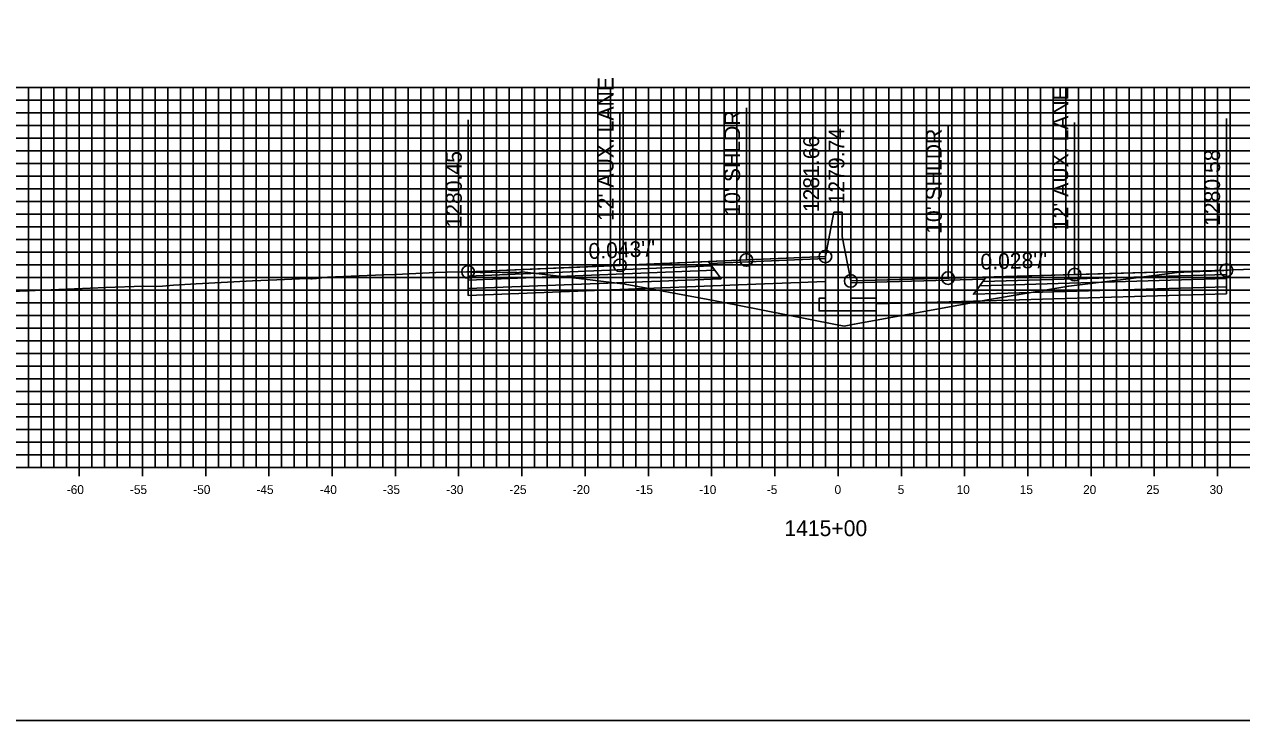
# Model space of a CAD drawing. Extents: x 674939 to 678919, y 750652 to 765176.
# Drawn here: x 678674.2 to 678770.4, y 757362.6 to 757417.6 of the extents above; entities that cross this region are included whole.
import ezdxf

# ---------------------------------------------------------------- set-up
doc = ezdxf.new("R2010")
doc.units = 0
for name, color, linetype in [('Level 10', 7, 'Continuous'), ('Level 17', 7, 'Continuous'), ('Level 18', 7, 'Continuous'), ('Level 19', 7, 'Continuous'), ('Level 20', 7, 'Continuous'), ('Level 22', 7, 'Continuous'), ('Level 23', 7, 'Continuous'), ('Level 4', 7, 'Continuous'), ('Level 8', 7, 'Continuous'), ('Level 9', 7, 'Continuous')]:
    doc.layers.add(name, color=color, linetype=linetype)

msp = doc.modelspace()

# ---------------------------------------------------------------- linework, layer by layer
at = {"layer": 'Level 10'}
msp.add_lwpolyline([(678673.204, 757396.454), (678680.637, 757396.759), (678683.613, 757396.86), (678684.619, 757396.855), (678685.125, 757396.867), (678685.988, 757396.947), (678687.79, 757397.046), (678692.244, 757397.286), (678693.542, 757397.337), (678696.557, 757397.466), (678696.844, 757397.454), (678696.957, 757397.449), (678697.296, 757397.481), (678698.157, 757397.57), (678701.312, 757397.704), (678702.614, 757397.757), (678703.576, 757397.798), (678706.73, 757397.946), (678707.615, 757397.971), (678709.191, 757398.006), (678709.281, 757398.001), (678709.304, 757398.002), (678709.474, 757397.988), (678710.244, 757397.952), (678710.471, 757397.951), (678710.641, 757397.958), (678711.644, 757397.973), (678711.984, 757397.962), (678712.987, 757397.938), (678713.101, 757397.938), (678713.158, 757397.933), (678713.301, 757397.946), (678713.424, 757397.975), (678713.567, 757398.013), (678719.143, 757397.336), (678721.689, 757397.02), (678728.253, 757395.813), (678730.436, 757395.408), (678738.318, 757393.85), (678739.006, 757393.714), (678739.804, 757393.856), (678748.937, 757395.534), (678750.191, 757395.754), (678756.762, 757396.881), (678761.483, 757397.458), (678765.331, 757397.947), (678766.427, 757397.99), (678767.839, 757398.06), (678768.056, 757398.056), (678768.514, 757398.074), (678769.02, 757398.115), (678769.228, 757398.127), (678769.372, 757398.139), (678769.715, 757398.158), (678771.464, 757398.211)], dxfattribs=at)
at = {"layer": 'Level 17'}
for points in [[(678738.203, 757402.714), (678737.533, 757399.214)], [(678738.203, 757402.714), (678738.203, 757402.714)], [(678738.203, 757402.714), (678738.863, 757402.714)], [(678738.863, 757402.714), (678738.863, 757400.787)], [(678738.863, 757400.787), (678739.533, 757397.287)], [(678737.533, 757399.214), (678737.533, 757395.912), (678737.033, 757395.912), (678737.033, 757394.912), (678741.533, 757394.912), (678741.533, 757395.912), (678739.533, 757395.912), (678739.533, 757397.287)]]:
    msp.add_lwpolyline(points, dxfattribs=at)
at = {"layer": 'Level 18'}
for points in [[(678737.533, 757399.214), (678731.281, 757398.945), (678721.281, 757398.516), (678709.281, 757398.001)], [(678769.228, 757398.127), (678757.228, 757397.787), (678747.228, 757397.504), (678739.533, 757397.287)]]:
    msp.add_lwpolyline(points, dxfattribs=at)
for points in [[(678709.281, 757398.001), (678709.281, 757397.671), (678728.531, 757398.477), (678728.281, 757398.817)], [(678728.399, 757398.656), (678737.533, 757399.054), (678737.533, 757399.214), (678728.281, 757398.817)], [(678750.111, 757397.429), (678739.533, 757397.127), (678739.533, 757397.287), (678750.228, 757397.589)], [(678769.228, 757398.127), (678769.228, 757397.797), (678749.978, 757397.249), (678750.228, 757397.589)]]:
    msp.add_lwpolyline(points, close=True, dxfattribs=at)
at = {"layer": 'Level 19'}
for points in [[(678709.281, 757397.671), (678709.281, 757397.341), (678728.781, 757398.137), (678728.531, 757398.477)], [(678709.281, 757397.341), (678709.281, 757396.681), (678729.281, 757397.457), (678728.781, 757398.137)], [(678769.228, 757397.467), (678769.228, 757396.807), (678749.228, 757396.229), (678749.728, 757396.909)], [(678769.228, 757397.797), (678769.228, 757397.467), (678749.728, 757396.909), (678749.978, 757397.249)]]:
    msp.add_lwpolyline(points, close=True, dxfattribs=at)
for points in [[(678709.281, 757396.681), (678709.281, 757396.141), (678729.281, 757396.917)], [(678729.281, 757396.917), (678737.533, 757397.237)], [(678769.228, 757396.807), (678769.23, 757396.267), (678749.228, 757395.689)], [(678749.228, 757395.689), (678741.533, 757395.467)]]:
    msp.add_lwpolyline(points, dxfattribs=at)
at = {"layer": 'Level 20'}
for p, q in [((678638.533, 757412.551), (678838.533, 757412.551)), ((678674.533, 757382.551), (678674.533, 757412.551)), ((678675.533, 757382.551), (678675.533, 757412.551)), ((678676.533, 757382.551), (678676.533, 757412.551)), ((678677.533, 757382.551), (678677.533, 757412.551)), ((678678.533, 757382.551), (678678.533, 757412.551)), ((678679.533, 757382.551), (678679.533, 757412.551)), ((678680.533, 757382.551), (678680.533, 757412.551)), ((678681.533, 757382.551), (678681.533, 757412.551)), ((678682.533, 757382.551), (678682.533, 757412.551)), ((678683.533, 757382.551), (678683.533, 757412.551)), ((678684.533, 757382.551), (678684.533, 757412.551)), ((678685.533, 757382.551), (678685.533, 757412.551)), ((678686.533, 757382.551), (678686.533, 757412.551)), ((678687.533, 757382.551), (678687.533, 757412.551)), ((678688.533, 757382.551), (678688.533, 757412.551)), ((678689.533, 757382.551), (678689.533, 757412.551)), ((678690.533, 757382.551), (678690.533, 757412.551)), ((678691.533, 757382.551), (678691.533, 757412.551)), ((678692.533, 757382.551), (678692.533, 757412.551)), ((678693.533, 757382.551), (678693.533, 757412.551)), ((678694.533, 757382.551), (678694.533, 757412.551)), ((678695.533, 757382.551), (678695.533, 757412.551)), ((678696.533, 757382.551), (678696.533, 757412.551)), ((678697.533, 757382.551), (678697.533, 757412.551)), ((678698.533, 757382.551), (678698.533, 757412.551)), ((678699.533, 757382.551), (678699.533, 757412.551)), ((678700.533, 757382.551), (678700.533, 757412.551)), ((678701.533, 757382.551), (678701.533, 757412.551)), ((678702.533, 757382.551), (678702.533, 757412.551)), ((678703.533, 757382.551), (678703.533, 757412.551)), ((678704.533, 757382.551), (678704.533, 757412.551)), ((678705.533, 757382.551), (678705.533, 757412.551)), ((678706.533, 757382.551), (678706.533, 757412.551)), ((678707.533, 757382.551), (678707.533, 757412.551)), ((678708.533, 757382.551), (678708.533, 757412.551)), ((678709.533, 757382.551), (678709.533, 757412.551)), ((678710.533, 757382.551), (678710.533, 757412.551)), ((678711.533, 757382.551), (678711.533, 757412.551)), ((678712.533, 757382.551), (678712.533, 757412.551)), ((678713.533, 757382.551), (678713.533, 757412.551)), ((678714.533, 757382.551), (678714.533, 757412.551)), ((678715.533, 757382.551), (678715.533, 757412.551)), ((678716.533, 757382.551), (678716.533, 757412.551)), ((678717.533, 757382.551), (678717.533, 757412.551)), ((678718.533, 757382.551), (678718.533, 757412.551)), ((678719.533, 757382.551), (678719.533, 757412.551)), ((678720.533, 757382.551), (678720.533, 757412.551)), ((678721.533, 757382.551), (678721.533, 757412.551)), ((678722.533, 757382.551), (678722.533, 757412.551)), ((678723.533, 757382.551), (678723.533, 757412.551)), ((678724.533, 757382.551), (678724.533, 757412.551)), ((678725.533, 757382.551), (678725.533, 757412.551)), ((678726.533, 757382.551), (678726.533, 757412.551)), ((678727.533, 757382.551), (678727.533, 757412.551)), ((678728.533, 757382.551), (678728.533, 757412.551)), ((678729.533, 757382.551), (678729.533, 757412.551)), ((678730.533, 757382.551), (678730.533, 757412.551)), ((678731.533, 757382.551), (678731.533, 757412.551)), ((678732.533, 757382.551), (678732.533, 757412.551)), ((678733.533, 757382.551), (678733.533, 757412.551)), ((678734.533, 757382.551), (678734.533, 757412.551)), ((678735.533, 757382.551), (678735.533, 757412.551)), ((678736.533, 757382.551), (678736.533, 757412.551)), ((678737.533, 757382.551), (678737.533, 757412.551)), ((678738.533, 757382.551), (678738.533, 757412.551)), ((678739.533, 757382.551), (678739.533, 757412.551)), ((678740.533, 757382.551), (678740.533, 757412.551)), ((678741.533, 757382.551), (678741.533, 757412.551)), ((678742.533, 757382.551), (678742.533, 757412.551)), ((678743.533, 757382.551), (678743.533, 757412.551)), ((678744.533, 757382.551), (678744.533, 757412.551)), ((678745.533, 757382.551), (678745.533, 757412.551)), ((678746.533, 757382.551), (678746.533, 757412.551)), ((678747.533, 757382.551), (678747.533, 757412.551)), ((678748.533, 757382.551), (678748.533, 757412.551)), ((678749.533, 757382.551), (678749.533, 757412.551)), ((678750.533, 757382.551), (678750.533, 757412.551)), ((678751.533, 757382.551), (678751.533, 757412.551)), ((678752.533, 757382.551), (678752.533, 757412.551)), ((678753.533, 757382.551), (678753.533, 757412.551)), ((678754.533, 757382.551), (678754.533, 757412.551)), ((678755.533, 757382.551), (678755.533, 757412.551)), ((678756.533, 757382.551), (678756.533, 757412.551)), ((678757.533, 757382.551), (678757.533, 757412.551)), ((678758.533, 757382.551), (678758.533, 757412.551)), ((678759.533, 757382.551), (678759.533, 757412.551)), ((678760.533, 757382.551), (678760.533, 757412.551)), ((678761.533, 757382.551), (678761.533, 757412.551)), ((678762.533, 757382.551), (678762.533, 757412.551)), ((678763.533, 757382.551), (678763.533, 757412.551)), ((678764.533, 757382.551), (678764.533, 757412.551)), ((678765.533, 757382.551), (678765.533, 757412.551)), ((678766.533, 757382.551), (678766.533, 757412.551)), ((678767.533, 757382.551), (678767.533, 757412.551)), ((678768.533, 757382.551), (678768.533, 757412.551)), ((678769.533, 757382.551), (678769.533, 757412.551)), ((678638.533, 757411.551), (678838.533, 757411.551)), ((678638.533, 757410.551), (678838.533, 757410.551)), ((678638.533, 757409.551), (678838.533, 757409.551)), ((678638.533, 757408.551), (678838.533, 757408.551)), ((678638.533, 757407.551), (678838.533, 757407.551)), ((678638.533, 757406.551), (678838.533, 757406.551)), ((678638.533, 757405.551), (678838.533, 757405.551)), ((678638.533, 757404.551), (678838.533, 757404.551)), ((678638.533, 757403.551), (678838.533, 757403.551)), ((678638.533, 757402.551), (678838.533, 757402.551)), ((678638.533, 757401.551), (678838.533, 757401.551)), ((678638.533, 757400.551), (678838.533, 757400.551)), ((678638.533, 757399.551), (678838.533, 757399.551)), ((678638.533, 757398.551), (678838.533, 757398.551)), ((678638.533, 757397.551), (678838.533, 757397.551)), ((678638.533, 757396.551), (678838.533, 757396.551)), ((678638.533, 757395.551), (678838.533, 757395.551)), ((678638.533, 757394.551), (678838.533, 757394.551)), ((678638.533, 757393.551), (678838.533, 757393.551)), ((678638.533, 757392.551), (678838.533, 757392.551)), ((678638.533, 757391.551), (678838.533, 757391.551)), ((678638.533, 757390.551), (678838.533, 757390.551)), ((678638.533, 757389.551), (678838.533, 757389.551)), ((678638.533, 757388.551), (678838.533, 757388.551)), ((678638.533, 757387.551), (678838.533, 757387.551)), ((678638.533, 757386.551), (678838.533, 757386.551)), ((678638.533, 757385.551), (678838.533, 757385.551)), ((678638.533, 757384.551), (678838.533, 757384.551)), ((678638.533, 757383.551), (678838.533, 757383.551)), ((678638.533, 757382.551), (678838.533, 757382.551))]:
    msp.add_line(p, q, dxfattribs=at)
at = {"layer": 'Level 23'}
for p, q in [((678731.281, 757398.945), (678731.281, 757410.945)), ((678737.533, 757399.214), (678737.533, 757411.214)), ((678709.281, 757398.001), (678709.281, 757410.001)), ((678721.281, 757398.516), (678721.281, 757410.516)), ((678769.228, 757398.127), (678769.228, 757410.127)), ((678739.533, 757397.287), (678739.533, 757409.287)), ((678747.228, 757397.504), (678747.228, 757409.504)), ((678757.228, 757397.787), (678757.228, 757409.787))]:
    msp.add_line(p, q, dxfattribs=at)
at = {"layer": 'Level 4'}
msp.add_lwpolyline([(678578.533, 757362.551), (678918.533, 757362.551), (678918.533, 757582.551), (678578.533, 757582.551)], close=True, dxfattribs=at)
for centre in [(678731.281, 757398.945), (678737.533, 757399.214), (678709.281, 757398.001), (678721.281, 757398.516), (678769.228, 757398.127), (678739.533, 757397.287), (678747.228, 757397.504), (678757.228, 757397.787)]:
    msp.add_circle(centre, 0.5, dxfattribs=at)
at = {"layer": 'Level 8'}
for p, q in [((678678.533, 757381.851), (678678.533, 757383.251)), ((678683.533, 757381.851), (678683.533, 757383.251)), ((678688.533, 757381.851), (678688.533, 757383.251)), ((678693.533, 757381.851), (678693.533, 757383.251)), ((678698.533, 757381.851), (678698.533, 757383.251)), ((678703.533, 757381.851), (678703.533, 757383.251)), ((678708.533, 757381.851), (678708.533, 757383.251)), ((678713.533, 757381.851), (678713.533, 757383.251)), ((678718.533, 757381.851), (678718.533, 757383.251)), ((678723.533, 757381.851), (678723.533, 757383.251)), ((678728.533, 757381.851), (678728.533, 757383.251)), ((678733.533, 757381.851), (678733.533, 757383.251)), ((678738.533, 757381.851), (678738.533, 757383.251)), ((678743.533, 757381.851), (678743.533, 757383.251)), ((678748.533, 757381.851), (678748.533, 757383.251)), ((678753.533, 757381.851), (678753.533, 757383.251)), ((678758.533, 757381.851), (678758.533, 757383.251)), ((678763.533, 757381.851), (678763.533, 757383.251)), ((678768.533, 757381.851), (678768.533, 757383.251)), ((678638.533, 757382.551), (678838.533, 757382.551))]:
    msp.add_line(p, q, dxfattribs=at)

# ---------------------------------------------------------------- texts
at = {"layer": 'Level 22'}
for s, rotation, p in [("0.043'/'", 2.45685, (678718.823, 757399.011)), ("0.028'/'", 1.62016, (678749.803, 757398.177))]:
    msp.add_text(s, height=1.25, rotation=rotation, dxfattribs=at).set_placement(p)
at = {"layer": 'Level 23'}
for s, p in [("12' AUX. LANE", (678720.781, 757402.016)), ("12' AUX. LANE", (678756.728, 757401.287)), ("10' SHLDR", (678730.781, 757402.445)), ('1279.74', (678739.033, 757403.329)), ("10' SHLDR", (678746.728, 757401.004)), ('1281.66', (678737.033, 757402.714)), ('1280.45', (678708.781, 757401.501)), ('1280.58', (678768.728, 757401.627))]:
    msp.add_text(s, height=1.25, rotation=90, dxfattribs=at).set_placement(p)
at = {"layer": 'Level 9'}
for s, height, p in [('-60', 0.7, (678677.552, 757380.451)), ('-55', 0.7, (678682.546, 757380.451)), ('-50', 0.7, (678687.552, 757380.451)), ('-45', 0.7, (678692.546, 757380.451)), ('-40', 0.7, (678697.552, 757380.451)), ('-35', 0.7, (678702.546, 757380.451)), ('-30', 0.7, (678707.552, 757380.451)), ('-25', 0.7, (678712.546, 757380.451)), ('-20', 0.7, (678717.552, 757380.451)), ('-15', 0.7, (678722.546, 757380.451)), ('-10', 0.7, (678727.552, 757380.451)), ('-5', 0.7, (678732.896, 757380.451)), ('0', 0.7, (678738.252, 757380.451)), ('5', 0.7, (678743.246, 757380.451)), ('10', 0.7, (678747.902, 757380.451)), ('15', 0.7, (678752.896, 757380.451)), ('20', 0.7, (678757.902, 757380.451)), ('25', 0.7, (678762.896, 757380.451)), ('30', 0.7, (678767.902, 757380.451)), ('1415+00', 1.25, (678734.281, 757377.126))]:
    msp.add_text(s, height=height, dxfattribs=at).set_placement(p)

doc.saveas('drawing.dxf')
